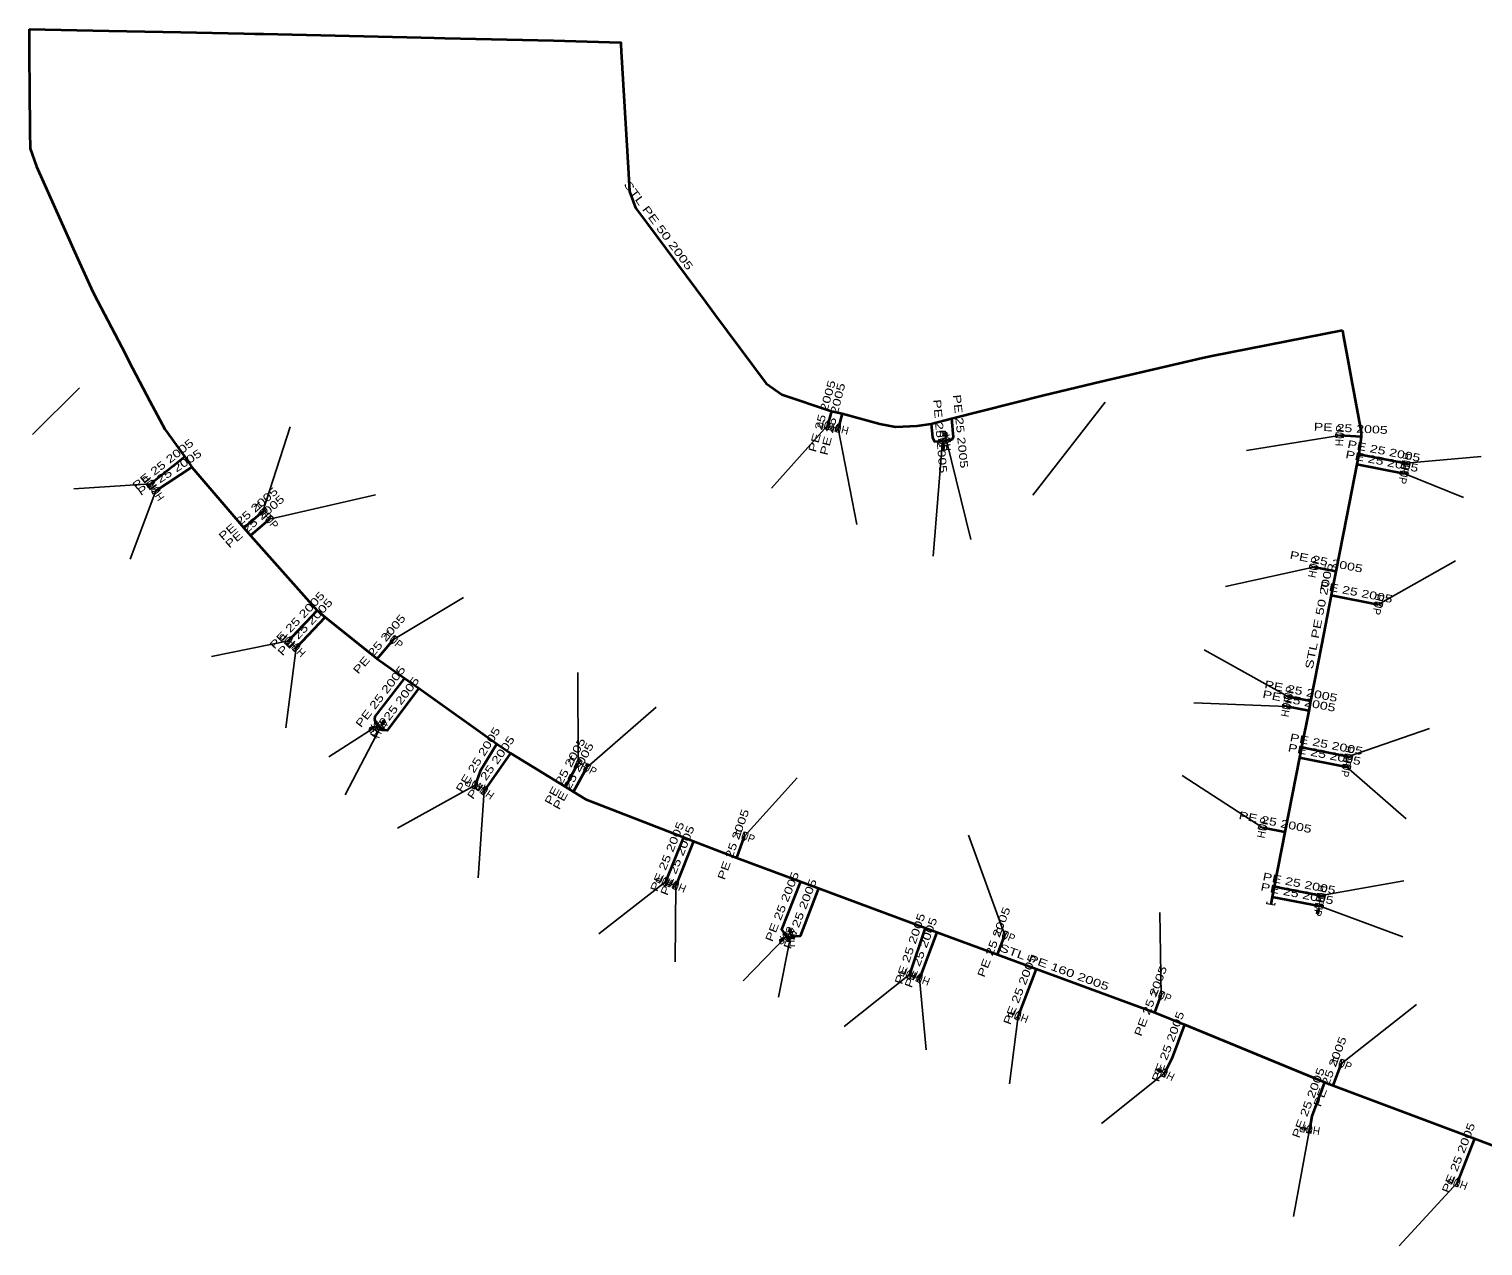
# Model space of a CAD drawing. Extents: x -737484 to -734496, y -1033882 to -1030666.
# Drawn here: x -736940.4 to -736755, y -1030906.1 to -1030750.8 of the extents above; entities that cross this region are included whole.
import ezdxf
from ezdxf.enums import TextEntityAlignment as Align

# ---------------------------------------------------------------- set-up
doc = ezdxf.new("R2010")
doc.units = 0
doc.header["$LTSCALE"] = 0.4
for name, color, linetype, lineweight in [('1', 7, 'Continuous', 13), ('22', 7, 'Continuous', 25), ('5', 7, 'Continuous', 35), ('7', 7, 'Continuous', 35)]:
    doc.layers.add(name, color=color, linetype=linetype, lineweight=lineweight)
doc.layers.add('2', color=7, linetype='Continuous')

msp = doc.modelspace()

# ---------------------------------------------------------------- linework, layer by layer
at = {"layer": '1'}
for p, q in [((-736823.405, -1030802.75), (-736823.435, -1030802.401)), ((-736823.944, -1030803.968), (-736823.92, -1030804.317)), ((-736823.91, -1030803.39), (-736823.875, -1030803.888)), ((-736823.43, -1030803.33), (-736823.473, -1030802.831)), ((-736895.64, -1030840.01), (-736895.413, -1030839.564)), ((-736895.312, -1030839.531), (-736895.153, -1030839.219)), ((-736896.578, -1030839.895), (-736896.9, -1030840.032)), ((-736896.02, -1030839.74), (-736896.48, -1030839.935)), ((-736776.073, -1030863.26), (-736776.14, -1030863.603)), ((-736775.89, -1030862.71), (-736775.985, -1030863.2)), ((-736844.329, -1030866.857), (-736844.612, -1030867.063)), ((-736843.82, -1030866.58), (-736844.224, -1030866.873)), ((-736843.32, -1030866.64), (-736843.346, -1030866.14)), ((-736843.275, -1030866.061), (-736843.293, -1030865.712)), ((-736796.098, -1030883.712), (-736796.41, -1030883.553)), ((-736795.62, -1030884.04), (-736796.065, -1030883.813)), ((-736777.656, -1030891.075), (-736778.001, -1030891.021)), ((-736777.1, -1030891.24), (-736777.593, -1030891.161))]:
    msp.add_line(p, q, dxfattribs=at)
for points in [[(-736838.535, -1030801.955), (-736838.92, -1030801.845), (-736838.259, -1030800.994), (-736838.644, -1030800.884)], [(-736837.146, -1030802.333), (-736837.535, -1030802.236), (-736836.904, -1030801.363), (-736837.293, -1030801.266)], [(-736823.517, -1030802.333), (-736823.666, -1030802.346), (-736823.623, -1030802.844), (-736823.473, -1030802.831)], [(-736823.517, -1030802.333), (-736823.367, -1030802.32), (-736823.324, -1030802.818), (-736823.473, -1030802.831)], [(-736823.476, -1030802.368), (-736823.402, -1030802.361), (-736823.365, -1030802.785), (-736823.439, -1030802.791)], [(-736773.789, -1030802.893), (-736773.768, -1030802.494), (-736772.791, -1030802.945), (-736772.77, -1030802.546)], [(-736823.425, -1030803.155), (-736823.397, -1030803.554), (-736824.422, -1030803.225), (-736824.394, -1030803.624)], [(-736823.84, -1030804.387), (-736823.989, -1030804.398), (-736824.024, -1030803.899), (-736823.875, -1030803.888)], [(-736823.879, -1030804.352), (-736823.954, -1030804.357), (-736823.984, -1030803.933), (-736823.909, -1030803.928)], [(-736823.91, -1030803.572), (-736823.945, -1030803.174), (-736822.914, -1030803.485), (-736822.949, -1030803.087)], [(-736823.84, -1030804.387), (-736823.69, -1030804.377), (-736823.725, -1030803.878), (-736823.875, -1030803.888)], [(-736764.281, -1030806.139), (-736764.357, -1030806.531), (-736765.262, -1030805.948), (-736765.338, -1030806.34)], [(-736764.531, -1030807.449), (-736764.607, -1030807.841), (-736765.512, -1030807.258), (-736765.588, -1030807.65)], [(-736925.18, -1030809.325), (-736925.427, -1030809.01), (-736924.392, -1030808.709), (-736924.639, -1030808.394)], [(-736924.56, -1030810.2), (-736924.778, -1030809.864), (-736923.721, -1030809.655), (-736923.939, -1030809.319)], [(-736910.363, -1030811.911), (-736910.101, -1030812.212), (-736911.118, -1030812.567), (-736910.856, -1030812.868)], [(-736909.533, -1030812.901), (-736909.271, -1030813.202), (-736910.288, -1030813.557), (-736910.026, -1030813.858)], [(-736777.118, -1030819.61), (-736777.042, -1030819.218), (-736776.137, -1030819.801), (-736776.061, -1030819.409)], [(-736767.821, -1030824.149), (-736767.897, -1030824.541), (-736768.802, -1030823.958), (-736768.878, -1030824.35)], [(-736907.524, -1030829.382), (-736907.817, -1030829.109), (-736906.842, -1030828.65), (-736907.135, -1030828.377)], [(-736893.791, -1030828.228), (-736893.485, -1030828.485), (-736894.434, -1030828.994), (-736894.128, -1030829.251)], [(-736906.563, -1030830.268), (-736906.851, -1030829.99), (-736905.868, -1030829.549), (-736906.156, -1030829.271)], [(-736780.328, -1030836.12), (-736780.252, -1030835.728), (-736779.347, -1030836.311), (-736779.271, -1030835.919)], [(-736780.578, -1030837.37), (-736780.502, -1030836.978), (-736779.597, -1030837.561), (-736779.521, -1030837.169)], [(-736895.64, -1030840.122), (-736896.008, -1030840.278), (-736896.031, -1030839.201), (-736896.399, -1030839.357)], [(-736896.176, -1030839.961), (-736895.994, -1030839.604), (-736895.285, -1030840.415), (-736895.103, -1030840.058)], [(-736895.186, -1030839.118), (-736895.319, -1030839.05), (-736895.546, -1030839.496), (-736895.413, -1030839.564)], [(-736895.186, -1030839.118), (-736895.052, -1030839.187), (-736895.279, -1030839.632), (-736895.413, -1030839.564)], [(-736895.17, -1030839.169), (-736895.103, -1030839.203), (-736895.296, -1030839.582), (-736895.363, -1030839.548)], [(-736896.94, -1030840.13), (-736896.999, -1030839.992), (-736896.538, -1030839.797), (-736896.48, -1030839.935)], [(-736896.919, -1030840.081), (-736896.949, -1030840.012), (-736896.558, -1030839.846), (-736896.528, -1030839.915)], [(-736896.94, -1030840.13), (-736896.881, -1030840.268), (-736896.421, -1030840.073), (-736896.48, -1030839.935)], [(-736771.621, -1030843.549), (-736771.697, -1030843.941), (-736772.602, -1030843.358), (-736772.678, -1030843.75)], [(-736870.321, -1030843.954), (-736869.968, -1030844.142), (-736870.791, -1030844.837), (-736870.438, -1030845.025)], [(-736869.251, -1030844.524), (-736868.898, -1030844.712), (-736869.721, -1030845.407), (-736869.368, -1030845.595)], [(-736771.871, -1030844.849), (-736771.947, -1030845.241), (-736772.852, -1030844.658), (-736772.928, -1030845.05)], [(-736883.523, -1030847.828), (-736883.898, -1030847.691), (-736883.181, -1030846.888), (-736883.556, -1030846.751)], [(-736882.502, -1030848.554), (-736882.83, -1030848.324), (-736881.929, -1030847.735), (-736882.257, -1030847.505)], [(-736783.618, -1030852.83), (-736783.542, -1030852.438), (-736782.637, -1030853.021), (-736782.561, -1030852.629)], [(-736849.186, -1030853.261), (-736848.811, -1030853.398), (-736849.528, -1030854.201), (-736849.153, -1030854.338)], [(-736859.241, -1030860.158), (-736859.612, -1030860.008), (-736858.867, -1030859.231), (-736859.238, -1030859.081)], [(-736857.941, -1030860.648), (-736858.312, -1030860.498), (-736857.567, -1030859.721), (-736857.938, -1030859.571)], [(-736775.101, -1030861.299), (-736775.177, -1030861.691), (-736776.082, -1030861.108), (-736776.158, -1030861.5)], [(-736775.361, -1030862.609), (-736775.437, -1030863.001), (-736776.342, -1030862.418), (-736776.418, -1030862.81)], [(-736776.08, -1030863.691), (-736776.228, -1030863.663), (-736776.132, -1030863.172), (-736775.985, -1030863.2)], [(-736776.109, -1030863.647), (-736776.183, -1030863.632), (-736776.102, -1030863.215), (-736776.028, -1030863.23)], [(-736776.08, -1030863.691), (-736775.933, -1030863.72), (-736775.838, -1030863.229), (-736775.985, -1030863.2)], [(-736844.629, -1030867.167), (-736844.717, -1030867.046), (-736844.312, -1030866.752), (-736844.224, -1030866.873)], [(-736844.62, -1030867.115), (-736844.664, -1030867.054), (-736844.32, -1030866.805), (-736844.276, -1030866.865)], [(-736844.629, -1030867.167), (-736844.54, -1030867.289), (-736844.136, -1030866.995), (-736844.224, -1030866.873)], [(-736843.364, -1030866.866), (-736843.687, -1030867.102), (-736843.952, -1030866.057), (-736844.275, -1030866.293)], [(-736843.808, -1030866.865), (-736843.829, -1030866.466), (-736842.81, -1030866.813), (-736842.831, -1030866.414)], [(-736843.372, -1030865.641), (-736843.522, -1030865.649), (-736843.495, -1030866.148), (-736843.346, -1030866.14)], [(-736843.372, -1030865.641), (-736843.222, -1030865.633), (-736843.196, -1030866.132), (-736843.346, -1030866.14)], [(-736843.333, -1030865.677), (-736843.258, -1030865.673), (-736843.236, -1030866.097), (-736843.311, -1030866.101)], [(-736815.977, -1030865.891), (-736815.604, -1030866.034), (-736816.335, -1030866.825), (-736815.962, -1030866.968)], [(-736828.103, -1030872.007), (-736828.481, -1030871.877), (-736827.778, -1030871.062), (-736828.156, -1030870.932)], [(-736826.842, -1030872.498), (-736827.215, -1030872.355), (-736826.484, -1030871.564), (-736826.857, -1030871.421)], [(-736796.037, -1030873.561), (-736795.664, -1030873.704), (-736796.395, -1030874.495), (-736796.022, -1030874.638)], [(-736814.272, -1030877.278), (-736814.645, -1030877.135), (-736813.914, -1030876.344), (-736814.287, -1030876.201)], [(-736773.037, -1030882.261), (-736772.664, -1030882.404), (-736773.395, -1030883.195), (-736773.022, -1030883.338)], [(-736796.511, -1030883.586), (-736796.579, -1030883.719), (-736796.133, -1030883.946), (-736796.065, -1030883.813)], [(-736796.511, -1030883.586), (-736796.442, -1030883.452), (-736795.997, -1030883.679), (-736796.065, -1030883.813)], [(-736796.46, -1030883.57), (-736796.426, -1030883.503), (-736796.047, -1030883.696), (-736796.081, -1030883.763)], [(-736795.668, -1030884.576), (-736796.025, -1030884.394), (-736795.214, -1030883.685), (-736795.571, -1030883.503)], [(-736778.087, -1030891.083), (-736778.111, -1030891.231), (-736777.617, -1030891.309), (-736777.593, -1030891.161)], [(-736778.087, -1030891.083), (-736778.064, -1030890.935), (-736777.57, -1030891.013), (-736777.593, -1030891.161)], [(-736778.044, -1030891.052), (-736778.032, -1030890.978), (-736777.612, -1030891.045), (-736777.624, -1030891.119)], [(-736776.98, -1030891.765), (-736777.375, -1030891.702), (-736776.824, -1030890.777), (-736777.219, -1030890.714)], [(-736758.262, -1030898.568), (-736758.635, -1030898.425), (-736757.904, -1030897.634), (-736758.277, -1030897.491)]]:
    msp.add_lwpolyline(points, close=True, dxfattribs=at)
msp.add_lwpolyline([(-736781.521, -1030862.369), (-736781.569, -1030862.615), (-736782.55, -1030862.424), (-736782.503, -1030862.179)], dxfattribs=at)
at = {"layer": '22'}
for p, q in [((-736934, -1030796.62), (-736940.011, -1030802.583)), ((-736803.19, -1030798.44), (-736812.385, -1030810.296)), ((-736910.61, -1030812.39), (-736907.149, -1030801.597)), ((-736838.59, -1030801.42), (-736845.757, -1030809.398)), ((-736837.22, -1030801.8), (-736834.832, -1030814.037)), ((-736823.91, -1030803.39), (-736825.105, -1030818.077)), ((-736823.43, -1030803.33), (-736820.316, -1030815.982)), ((-736773.28, -1030802.72), (-736785.148, -1030804.609)), ((-736764.81, -1030806.24), (-736755.218, -1030805.357)), ((-736765.06, -1030807.55), (-736757.463, -1030810.595)), ((-736924.91, -1030808.86), (-736934.724, -1030809.495)), ((-736924.25, -1030809.76), (-736927.526, -1030818.46)), ((-736909.78, -1030813.38), (-736896.225, -1030810.277)), ((-736768.35, -1030824.25), (-736758.51, -1030818.676)), ((-736776.59, -1030819.51), (-736787.842, -1030821.968)), ((-736893.96, -1030828.74), (-736885.037, -1030823.384)), ((-736907.33, -1030828.88), (-736917.172, -1030830.897)), ((-736906.36, -1030829.77), (-736907.702, -1030839.988)), ((-736779.8, -1030836.02), (-736790.536, -1030830.05)), ((-736870.38, -1030844.49), (-736870.453, -1030832.917)), ((-736869.31, -1030845.06), (-736860.458, -1030837.364)), ((-736780.05, -1030837.27), (-736791.882, -1030836.784)), ((-736896.02, -1030839.74), (-736902.21, -1030843.713)), ((-736895.64, -1030840.01), (-736900.135, -1030848.539)), ((-736772.15, -1030843.65), (-736761.802, -1030840.076)), ((-736772.4, -1030844.95), (-736764.795, -1030851.599)), ((-736849.17, -1030853.8), (-736842.465, -1030846.362)), ((-736783.09, -1030852.73), (-736793.379, -1030846.062)), ((-736883.54, -1030847.29), (-736893.434, -1030852.805)), ((-736882.38, -1030848.03), (-736883.143, -1030859.118)), ((-736815.97, -1030866.43), (-736820.616, -1030853.694)), ((-736859.24, -1030859.62), (-736867.756, -1030866.265)), ((-736775.63, -1030861.4), (-736765.095, -1030859.531)), ((-736857.94, -1030860.11), (-736858.028, -1030869.857)), ((-736796.03, -1030874.1), (-736796.222, -1030863.571)), ((-736775.89, -1030862.71), (-736765.195, -1030866.647)), ((-736843.82, -1030866.58), (-736849.349, -1030872.251)), ((-736843.32, -1030866.64), (-736844.859, -1030874.346)), ((-736828.13, -1030871.47), (-736836.479, -1030878.088)), ((-736826.85, -1030871.96), (-736826.003, -1030881.081)), ((-736814.28, -1030876.74), (-736815.378, -1030885.421)), ((-736773.03, -1030882.8), (-736763.479, -1030875.287)), ((-736795.62, -1030884.04), (-736803.643, -1030890.46)), ((-736777.1, -1030891.24), (-736779.162, -1030902.331)), ((-736758.27, -1030898.03), (-736765.691, -1030906.087))]:
    msp.add_line(p, q, dxfattribs=at)
at = {"layer": '5'}
for points in [[(-736940.43, -1030750.85), (-736930.26, -1030751.06), (-736921.09, -1030751.25), (-736913.03, -1030751.41), (-736911.63, -1030751.45), (-736910.51, -1030751.47), (-736890.44, -1030751.94), (-736888.77, -1030751.97), (-736887.4, -1030752.01), (-736873.54, -1030752.29), (-736864.97, -1030752.55), (-736864.96, -1030752.77), (-736864.9, -1030753.72), (-736864.03, -1030768.56), (-736863.85, -1030771.56), (-736863.08, -1030773.64), (-736861.68, -1030775.52), (-736854.17, -1030785.64), (-736853, -1030787.23), (-736846.43, -1030796.07), (-736844.44, -1030797.48), (-736838.07, -1030799.58), (-736836.74, -1030799.9), (-736831.93, -1030801.2), (-736829.92, -1030801.61), (-736827.17, -1030801.45), (-736825.36, -1030801.2), (-736822.79, -1030800.55), (-736810.99, -1030797.54), (-736803.73, -1030795.82), (-736790.76, -1030792.78), (-736789.58, -1030792.54), (-736772.92, -1030789.25)], [(-736940.43, -1030750.85), (-736940.4, -1030754.41), (-736940.37, -1030758.38), (-736940.32, -1030763.95), (-736940.3, -1030766.09), (-736939.5, -1030768.4), (-736934.97, -1030778.46), (-736934.42, -1030779.69), (-736932.3, -1030784.35), (-736931.7, -1030785.54), (-736928.62, -1030791.45), (-736927.24, -1030794.11), (-736925.02, -1030798.34), (-736923.11, -1030801.9), (-736920.55, -1030805.43), (-736919.67, -1030806.73), (-736913.03, -1030814.49), (-736912.19, -1030815.47), (-736903.69, -1030825.04), (-736902.65, -1030825.87), (-736896.04, -1030831.18), (-736892.56, -1030833.66), (-736890.7, -1030834.95), (-736880.75, -1030842.04), (-736879.03, -1030843.21), (-736872, -1030847.52), (-736870.97, -1030848.17), (-736869.46, -1030849.1), (-736856.97, -1030853.95), (-736855.68, -1030854.45), (-736850.16, -1030856.59), (-736842.05, -1030859.61), (-736839.75, -1030860.45), (-736826.12, -1030865.51), (-736824.64, -1030866.06), (-736816.92, -1030868.92), (-736811.98, -1030870.73), (-736796.86, -1030876.3), (-736793.06, -1030877.86), (-736775.21, -1030885.19), (-736774.1, -1030885.61), (-736756.09, -1030892.38), (-736744.26, -1030896.83)], [(-736772.92, -1030789.25), (-736772.76, -1030790.13), (-736772.17, -1030793.31), (-736771.74, -1030795.66), (-736770.51, -1030802.27), (-736770.52, -1030802.85), (-736770.81, -1030805.06), (-736771.06, -1030806.37), (-736772.38, -1030813.1), (-736773.74, -1030820.07), (-736774.36, -1030823.07), (-736775.6, -1030829.45), (-736776.98, -1030836.57), (-736777.22, -1030837.82), (-736778.14, -1030842.48), (-736778.39, -1030843.78), (-736780.25, -1030853.29), (-736781.61, -1030860.23), (-736781.87, -1030861.54), (-736782.06, -1030862.52)]]:
    msp.add_lwpolyline(points, dxfattribs=at)
at = {"layer": '7'}
for p, q in [((-736838.07, -1030799.58), (-736838.59, -1030801.42)), ((-736836.74, -1030799.9), (-736837.22, -1030801.8)), ((-736770.52, -1030802.85), (-736773.28, -1030802.72)), ((-736920.55, -1030805.43), (-736924.91, -1030808.86)), ((-736770.81, -1030805.06), (-736764.81, -1030806.24)), ((-736919.67, -1030806.73), (-736924.25, -1030809.76)), ((-736771.06, -1030806.37), (-736765.06, -1030807.55)), ((-736913.03, -1030814.49), (-736910.61, -1030812.39)), ((-736912.19, -1030815.47), (-736909.78, -1030813.38)), ((-736773.74, -1030820.07), (-736776.59, -1030819.51)), ((-736774.36, -1030823.07), (-736768.35, -1030824.25)), ((-736903.69, -1030825.04), (-736907.33, -1030828.88)), ((-736902.65, -1030825.87), (-736906.36, -1030829.77)), ((-736896.04, -1030831.18), (-736893.96, -1030828.74)), ((-736777.22, -1030837.82), (-736780.05, -1030837.27)), ((-736776.98, -1030836.57), (-736779.8, -1030836.02)), ((-736879.03, -1030843.21), (-736882.38, -1030848.03)), ((-736778.14, -1030842.48), (-736772.15, -1030843.65)), ((-736872, -1030847.52), (-736870.38, -1030844.49)), ((-736870.97, -1030848.17), (-736869.31, -1030845.06)), ((-736778.39, -1030843.78), (-736772.4, -1030844.95)), ((-736856.97, -1030853.95), (-736859.24, -1030859.62)), ((-736855.68, -1030854.45), (-736857.94, -1030860.11)), ((-736850.16, -1030856.59), (-736849.17, -1030853.8)), ((-736780.25, -1030853.29), (-736783.09, -1030852.73)), ((-736781.87, -1030861.54), (-736775.89, -1030862.71)), ((-736781.61, -1030860.23), (-736775.63, -1030861.4)), ((-736826.12, -1030865.51), (-736828.13, -1030871.47)), ((-736824.64, -1030866.06), (-736826.85, -1030871.96)), ((-736816.92, -1030868.92), (-736815.97, -1030866.43)), ((-736811.98, -1030870.73), (-736814.28, -1030876.74)), ((-736796.86, -1030876.3), (-736796.03, -1030874.1)), ((-736774.1, -1030885.61), (-736773.03, -1030882.8)), ((-736756.09, -1030892.38), (-736758.27, -1030898.03))]:
    msp.add_line(p, q, dxfattribs=at)
for points in [[(-736822.79, -1030800.55), (-736822.55, -1030802.93), (-736822.75, -1030803.27), (-736823.43, -1030803.33)], [(-736825.36, -1030801.2), (-736825.21, -1030802.95), (-736824.93, -1030803.47), (-736823.91, -1030803.39)], [(-736892.56, -1030833.66), (-736896.31, -1030838.55), (-736896.37, -1030838.91), (-736896.02, -1030839.74)], [(-736890.7, -1030834.95), (-736894.76, -1030840.35), (-736895.06, -1030840.31), (-736895.64, -1030840.01)], [(-736880.75, -1030842.04), (-736882.88, -1030845.5), (-736883.54, -1030847.29)], [(-736842.05, -1030859.61), (-736844.45, -1030865.7), (-736843.82, -1030866.58)], [(-736839.75, -1030860.45), (-736842.1, -1030866.57), (-736843.32, -1030866.64)], [(-736793.06, -1030877.86), (-736794.67, -1030882.18), (-736795.62, -1030884.04)], [(-736775.21, -1030885.19), (-736776.83, -1030889.52), (-736777.1, -1030891.24)]]:
    msp.add_lwpolyline(points, dxfattribs=at)

# ---------------------------------------------------------------- texts
at = {"layer": '2', "width": 0.95}
for rotation, p in [(164, (-736838.4517, -1030800.9392)), (166, (-736837.0985, -1030801.314)), (274, (-736824.4084, -1030803.4246)), (95, (-736822.9317, -1030803.2861)), (87, (-736772.7805, -1030802.7457)), (259, (-736765.5501, -1030807.4541)), (259, (-736765.3001, -1030806.1441)), (128, (-736924.516, -1030808.5513)), (123, (-736923.8309, -1030809.4868)), (311, (-736910.9864, -1030812.7175)), (311, (-736910.1564, -1030813.7075)), (79, (-736776.0989, -1030819.6049)), (259, (-736768.8401, -1030824.1541)), (137, (-736906.9885, -1030828.514)), (320, (-736894.2809, -1030829.1226)), (136, (-736906.0122, -1030829.4096)), (79, (-736779.5589, -1030837.3649)), (79, (-736779.3089, -1030836.1149)), (203, (-736896.2151, -1030839.2793)), (63, (-736895.1935, -1030840.2365)), (259, (-736772.6401, -1030843.5541)), (332, (-736870.6142, -1030844.931)), (332, (-736869.5442, -1030845.501)), (259, (-736772.8901, -1030844.8541)), (160, (-736883.3685, -1030846.8193)), (145, (-736882.0927, -1030847.6201)), (79, (-736782.5989, -1030852.8249)), (340, (-736849.3405, -1030854.2697)), (158, (-736859.0522, -1030859.156)), (158, (-736857.7522, -1030859.646)), (259, (-736776.3801, -1030862.6141)), (259, (-736776.1201, -1030861.3041)), (216, (-736844.1136, -1030866.175)), (93, (-736842.8205, -1030866.6127)), (339, (-736816.1487, -1030866.8963)), (161, (-736827.9667, -1030870.997)), (159, (-736826.6703, -1030871.4927)), (339, (-736796.2087, -1030874.5663)), (159, (-736814.1003, -1030876.2727)), (339, (-736773.2087, -1030883.2663)), (153, (-736795.3925, -1030883.5935)), (171, (-736777.0213, -1030890.7455)), (159, (-736758.0903, -1030897.5627))]:
    msp.add_text('HUP', height=1, rotation=rotation, dxfattribs=at).set_placement(p, align=Align.CENTER)
at = {"layer": '5', "width": 1.4}
for s, rotation, p in [('STL PE 50 2005', 306.579, (-736860.5528, -1030776.198)), ('STL PE 50 2005', 79.001, (-736775.4029, -1030825.8144)), ('STL PE 160 2005', 339.777, (-736809.8513, -1030870.9803))]:
    msp.add_text(s, height=1, rotation=rotation, dxfattribs=at).set_placement(p, align=Align.CENTER)
at = {"layer": '7', "width": 1.35}
for rotation, p in [(74.219, (-736838.8108, -1030800.3635)), (75.822, (-736837.4645, -1030800.727)), (274.899, (-736824.7172, -1030802.8353)), (275.758, (-736822.1175, -1030802.2248)), (357.303, (-736771.876, -1030802.2848)), (38.192, (-736923.0381, -1030806.7517)), (348.874, (-736767.713, -1030805.1591)), (33.488, (-736922.2359, -1030807.8273)), (348.874, (-736767.963, -1030806.4691)), (40.95, (-736912.1477, -1030813.0619)), (40.932, (-736911.3126, -1030814.047)), (348.884, (-736775.0679, -1030819.2993)), (46.532, (-736905.8729, -1030826.6155)), (348.892, (-736771.2578, -1030823.1686)), (46.43, (-736904.8665, -1030827.4751)), (49.554, (-736895.3797, -1030829.6349)), (52.516, (-736895.2166, -1030836.3028)), (53.062, (-736893.4159, -1030837.731)), (348.964, (-736778.2937, -1030835.8037)), (349.002, (-736778.5394, -1030837.0535)), (58.383, (-736882.7404, -1030844.3196)), (55.2, (-736881.1152, -1030845.3344)), (61.869, (-736871.6302, -1030845.7687)), (348.948, (-736775.0489, -1030842.574)), (61.908, (-736870.5803, -1030846.3794)), (348.948, (-736775.2989, -1030843.874)), (70.463, (-736850.1361, -1030855.0272)), (348.845, (-736781.5727, -1030852.5194)), (68.181, (-736858.5684, -1030856.5988)), (68.234, (-736857.2733, -1030857.0939)), (68.491, (-736843.9135, -1030862.9743)), (68.994, (-736841.6106, -1030863.9007)), (348.93, (-736778.7835, -1030861.6334)), (348.93, (-736778.5235, -1030860.3234)), (71.363, (-736827.5985, -1030868.3298)), (69.117, (-736816.9113, -1030867.4962)), (69.465, (-736826.2126, -1030868.8339)), (69.058, (-736813.5966, -1030873.5557)), (69.33, (-736796.912, -1030875.023)), (69.56, (-736794.6981, -1030880.8231)), (69.154, (-736774.0324, -1030884.0264)), (69.487, (-736776.7925, -1030887.9947)), (68.901, (-736757.6454, -1030895.0245))]:
    msp.add_text('PE 25 2005', height=1, rotation=rotation, dxfattribs=at).set_placement(p, align=Align.CENTER)

doc.saveas('drawing.dxf')
